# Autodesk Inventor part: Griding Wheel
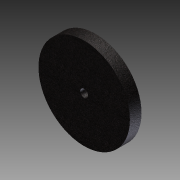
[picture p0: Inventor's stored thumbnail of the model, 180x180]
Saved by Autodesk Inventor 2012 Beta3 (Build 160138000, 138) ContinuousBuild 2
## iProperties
Created: 2010-12
Part Number: Griding Wheel
Document SubType Name: Modeling
Designer: Thom Tremblay
Density: 1 g/cm^3
Material: Default
Author: Thom Tremblay
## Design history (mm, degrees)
sketch "Sketch1"
  geometry: C1 r 6.413 at (0, 0); C2 r 74.93 at (0, 0); 1 further point
  constraints: 2 centre point, 2 coincident
  dimensions: "d0" = 12.827 diameter of C1; "d1" = 149.86 diameter of C2
extrude "Extrusion1" new body sketch "Sketch1" distance "d2" = 19.05; taper "d3" = 0 deg
body "Solid1"
